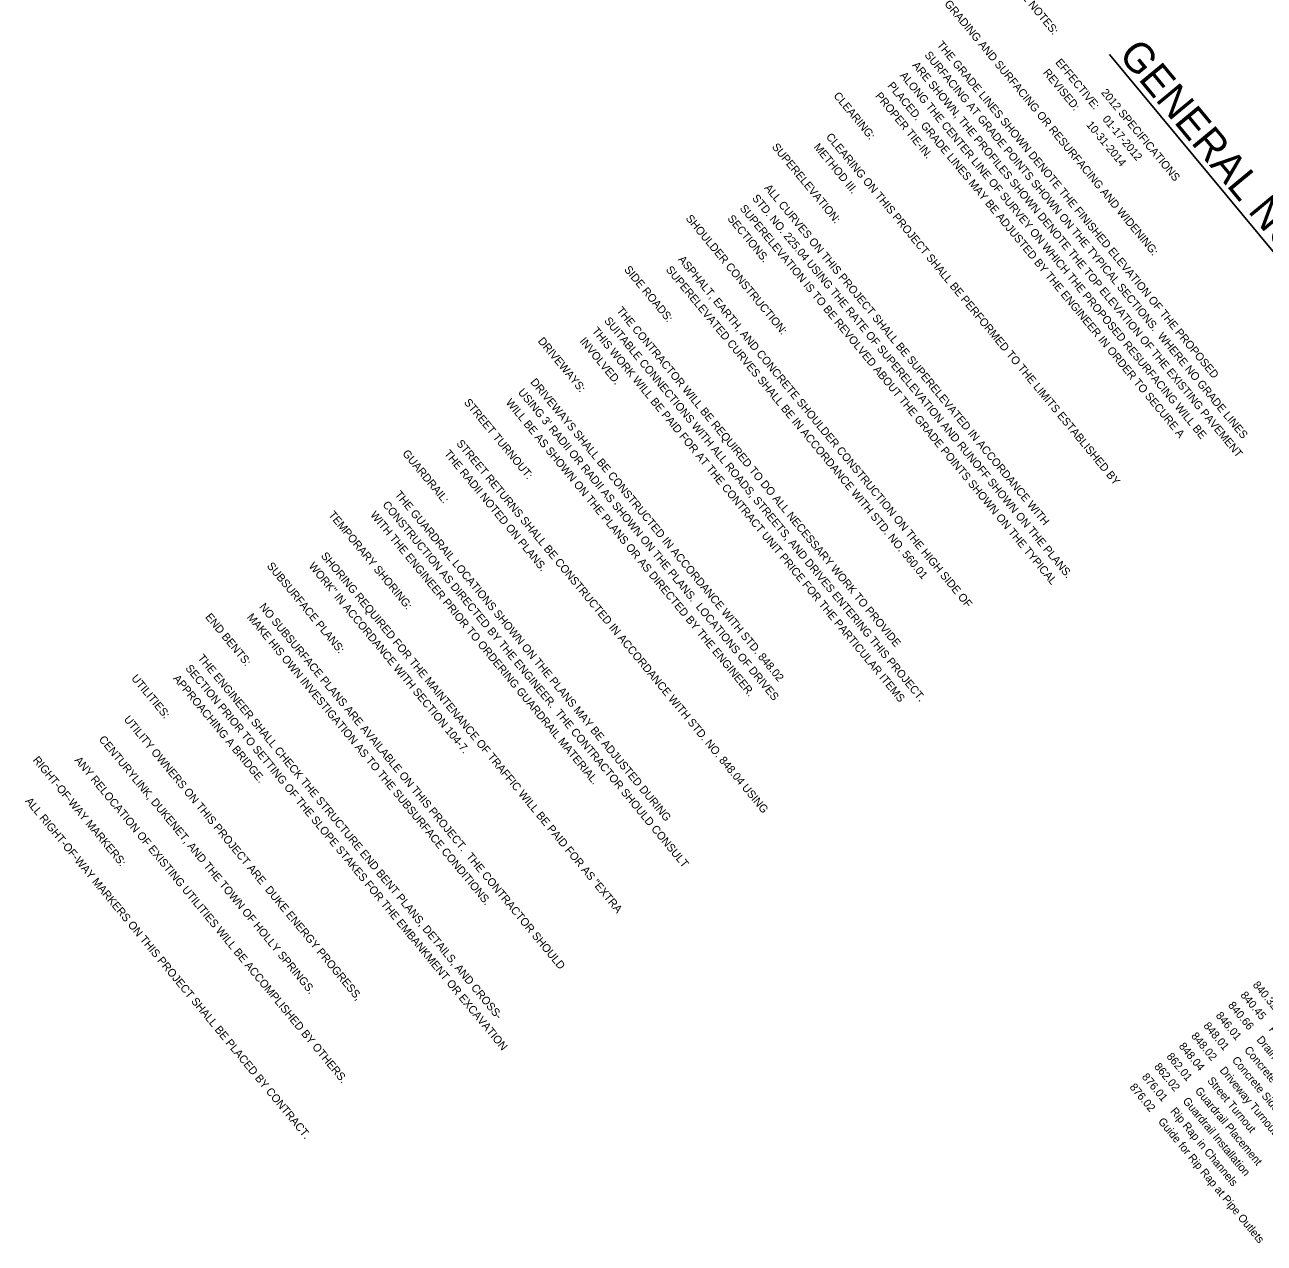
# Model space of a CAD drawing. Extents: x 2054826 to 2060231, y 685508 to 690809.
# Drawn here: x 2055445 to 2056065, y 686211 to 686820 of the extents above; entities that cross this region are included whole.
import ezdxf

# ---------------------------------------------------------------- set-up
doc = ezdxf.new("R2010")
doc.units = 0
doc.layers.add('Prop DSN Text', color=7, linetype='Continuous')

msp = doc.modelspace()

# ---------------------------------------------------------------- linework, layer by layer
at = {"layer": 'Prop DSN Text'}
msp.add_line((2055987.55, 686805.12), (2056106.09, 686662.16), dxfattribs=at)

# ---------------------------------------------------------------- texts
for s, height, p in [('GENERAL NOTES:                         2012 SPECIFICATIONS', 4, (2055929.43, 686850.68)), ('GRADING AND SURFACING OR RESURFACING AND WIDENING:  ', 4, (2055904.8, 686830.25)), ('         THE GRADE LINES SHOWN DENOTE THE FINISHED ELEVATION OF THE PROPOSED ', 4, (2055892.48, 686820.04)), ('GENERAL NOTES', 15, (2055991.67, 686804.7)), ('         SURFACING AT GRADE POINTS SHOWN ON THE TYPICAL SECTIONS.  WHERE NO GRADE LINES ', 4, (2055886.33, 686814.93)), ('         ARE SHOWN, THE PROFILES SHOWN DENOTE THE TOP ELEVATION OF THE EXISTING PAVEMENT ', 4, (2055880.17, 686809.83)), ('                                       REVISED:      10-31-2014', 4, (2055917.12, 686840.47)), ('                                       EFFECTIVE:    01-17-2012', 4, (2055923.27, 686845.57)), ('         PLACED.  GRADE LINES MAY BE ADJUSTED BY THE ENGINEER IN ORDER TO SECURE A ', 4, (2055867.85, 686799.62)), ('         ALONG THE CENTER LINE OF SURVEY ON WHICH THE PROPOSED RESURFACING WILL BE ', 4, (2055874.01, 686804.72)), ('CLEARING:  ', 4, (2055849.38, 686784.3)), ('         PROPER TIE-IN.  ', 4, (2055861.69, 686794.51)), ('SUPERELEVATION:  ', 4, (2055818.59, 686758.76)), ('         METHOD III.', 4, (2055830.9, 686768.98)), ('         CLEARING ON THIS PROJECT SHALL BE PERFORMED TO THE LIMITS ESTABLISHED BY ', 4, (2055837.06, 686774.08)), ('         ALL CURVES ON THIS PROJECT SHALL BE SUPERELEVATED IN ACCORDANCE WITH', 4, (2055806.27, 686748.55)), ('         SUPERELEVATION IS TO BE REVOLVED ABOUT THE GRADE POINTS SHOWN ON THE TYPICAL ', 4, (2055793.95, 686738.34)), ('         STD. NO. 225.04 USING THE RATE OF SUPERELEVATION AND RUNOFF SHOWN ON THE PLANS.', 4, (2055800.11, 686743.44)), ('SHOULDER CONSTRUCTION:  ', 4, (2055775.48, 686723.02)), ('         SECTIONS.  ', 4, (2055787.8, 686733.23)), ('SIDE ROADS:  ', 4, (2055744.69, 686697.48)), ('         SUPERELEVATED CURVES SHALL BE IN ACCORDANCE WITH STD. NO. 560.01', 4, (2055757.01, 686707.7)), ('         ASPHALT, EARTH, AND CONCRETE SHOULDER CONSTRUCTION ON THE HIGH SIDE OF', 4, (2055763.16, 686712.8)), ('         SUITABLE CONNECTIONS WITH ALL ROADS, STREETS, AND DRIVES ENTERING THIS PROJECT.  ', 4, (2055726.21, 686682.16)), ('         THE CONTRACTOR WILL BE REQUIRED TO DO ALL NECESSARY WORK TO PROVIDE ', 4, (2055732.37, 686687.27)), ('         THIS WORK WILL BE PAID FOR AT THE CONTRACT UNIT PRICE FOR THE PARTICULAR ITEMS ', 4, (2055720.06, 686677.06)), ('DRIVEWAYS:  ', 4, (2055701.58, 686661.74)), ('         INVOLVED.  ', 4, (2055713.9, 686671.95)), ('         DRIVEWAYS SHALL BE CONSTRUCTED IN ACCORDANCE WITH STD. 848.02', 4, (2055689.27, 686651.52)), ("         USING 3' RADII OR RADII AS SHOWN ON THE PLANS.  LOCATIONS OF DRIVES", 4, (2055683.11, 686646.42)), ('STREET TURNOUT:  ', 4, (2055664.63, 686631.1)), ('         WILL BE AS SHOWN ON THE PLANS OR AS DIRECTED BY THE ENGINEER.  ', 4, (2055676.95, 686641.31)), ('         STREET RETURNS SHALL BE CONSTRUCTED IN ACCORDANCE WITH STD. NO. 848.04 USING ', 4, (2055652.32, 686620.88)), ('GUARDRAIL:  ', 4, (2055633.84, 686605.56)), ('         THE RADII NOTED ON PLANS.  ', 4, (2055646.16, 686615.78)), ('         THE GUARDRAIL LOCATIONS SHOWN ON THE PLANS MAY BE ADJUSTED DURING ', 4, (2055621.53, 686595.35)), ('         CONSTRUCTION AS DIRECTED BY THE ENGINEER.  THE CONTRACTOR SHOULD CONSULT', 4, (2055615.37, 686590.24)), ('TEMPORARY SHORING:  ', 4, (2055596.89, 686574.92)), ('         WITH THE ENGINEER PRIOR TO ORDERING GUARDRAIL MATERIAL.', 4, (2055609.21, 686585.14)), ('         SHORING REQUIRED FOR THE MAINTENANCE OF TRAFFIC WILL BE PAID FOR AS "EXTRA ', 4, (2055584.58, 686564.71)), ('SUBSURFACE PLANS:      ', 4, (2055566.11, 686549.38)), ('         WORK" IN ACCORDANCE WITH SECTION 104-7.  ', 4, (2055578.42, 686559.6)), ('         NO SUBSURFACE PLANS ARE AVAILABLE ON THIS PROJECT.  THE CONTRACTOR SHOULD', 4, (2055553.78, 686539.18)), ('END BENTS:  ', 4, (2055535.31, 686523.86)), ('         MAKE HIS OWN INVESTIGATION AS TO THE SUBSURFACE CONDITIONS.', 4, (2055547.63, 686534.07)), ('         SECTION PRIOR TO SETTING OF THE SLOPE STAKES FOR THE EMBANKMENT OR EXCAVATION ', 4, (2055516.84, 686508.54)), ('         THE ENGINEER SHALL CHECK THE STRUCTURE END BENT PLANS, DETAILS, AND CROSS-', 4, (2055523, 686513.64)), ('UTILITIES:  ', 4, (2055498.36, 686493.22)), ('         APPROACHING A BRIDGE.  ', 4, (2055510.68, 686503.43)), ('         UTILITY OWNERS ON THIS PROJECT ARE  DUKE ENERGY PROGRESS,', 4, (2055486.05, 686483)), ('         CENTURYLINK, DUKENET, AND THE TOWN OF HOLLY SPRINGS.', 4, (2055473.57, 686472.99)), ('RIGHT-OF-WAY MARKERS:  ', 4, (2055449.1, 686452.37)), ('         ANY RELOCATION OF EXISTING UTILITIES WILL BE ACCOMPLISHED BY OTHERS.  ', 4, (2055461.42, 686462.58)), ('         ALL RIGHT-OF-WAY MARKERS ON THIS PROJECT SHALL BE PLACED BY CONTRACT.  ', 4, (2055436.78, 686442.15)), ('        840.32    Brick Junction Box - 12" thru 66" Pipe', 4, (2056051.35, 686349.17)), ('        840.45    Precast Drainage Structure', 4, (2056045.19, 686344.07)), ('        846.01    Concrete Curb, Gutter and Curb & Gutter', 4, (2056032.87, 686333.85)), ('        840.66    Drainage Structure Steps', 4, (2056039.03, 686338.96)), ('        848.01    Concrete Sidewalk', 4, (2056026.71, 686328.75)), ('        848.02    Driveway Turnout - Radius Type', 4, (2056020.56, 686323.64)), ('        848.04    Street Turnout', 4, (2056014.4, 686318.53)), ('        862.01    Guardrail Placement', 4, (2056008.24, 686313.43)), ('        876.01    Rip Rap in Channels', 4, (2055995.92, 686303.21)), ('        862.02    Guardrail Installation', 4, (2056002.08, 686308.32)), ('        876.02    Guide for Rip Rap at Pipe Outlets', 4, (2055989.77, 686298.11))]:
    msp.add_text(s, height=height, rotation=309.66721, dxfattribs=at).set_placement(p)

doc.saveas('drawing.dxf')
